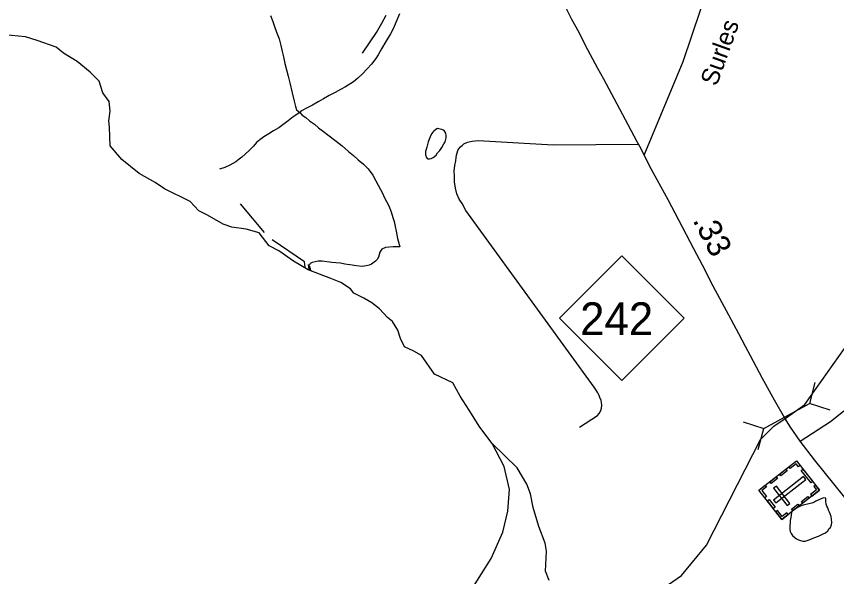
# Model space of a CAD drawing. Extents: x 2082433 to 2279600, y 546599 to 755198.
# Drawn here: x 2136702 to 2141084, y 579366 to 582358 of the extents above; entities that cross this region are included whole.
import ezdxf

# ---------------------------------------------------------------- set-up
doc = ezdxf.new("R2010")
doc.units = 0
for name, color, linetype in [('Exist Boundary Political CountyLine', 7, 'Continuous'), ('Exist Boundary Political Fire Districts', 7, 'Continuous'), ('Exist Cultural Cemetery CELL', 7, 'Continuous'), ('Exist Hydrographic Buffer Line', 7, 'Continuous'), ('Exist Hydrographic Creek Single Shore', 7, 'Continuous'), ('Exist Hydrographic Lake Shore', 7, 'Continuous'), ('Exist Hydrographic Misc Water Feature', 7, 'Continuous'), ('Exist Road Non-System Type 51', 7, 'Continuous'), ('Exist Road Primary NC Attributed', 7, 'Continuous'), ('Exist Road Primary NC Service Mileage Hundredths English Label', 7, 'Continuous'), ('Exist Road Primary NC Shield CELL', 7, 'Continuous'), ('Exist Road Primary NC Shield Number Label', 7, 'Continuous'), ('Exist Road Primary NC Structure Culvert CELL', 7, 'Continuous'), ('Exist Road Secondary Type 51 Attributed', 7, 'Continuous'), ('Exist Road Secondary Type 51 Label', 7, 'Continuous')]:
    doc.layers.add(name, color=color, linetype=linetype)

msp = doc.modelspace()

# ---------------------------------------------------------------- linework, layer by layer
at = {"layer": 'Exist Boundary Political CountyLine'}
msp.add_lwpolyline([(2139092.6, 579230.9), (2139238.1, 579462.3), (2139300.5, 579602.7), (2139327.7, 579714.5), (2139335.5, 579831.5), (2139307, 579953.7), (2139244.2, 580075.9), (2139178, 580164.1), (2139121.2, 580255.3), (2139072, 580328.8), (2139033, 580400.3), (2138936, 580446.6), (2138865.5, 580547.3), (2138825.3, 580569.6), (2138775.7, 580593.1), (2138753.9, 580637.4), (2138740.2, 580683), (2138711.7, 580728.6), (2138683.8, 580750.6), (2138642, 580796.5), (2138601, 580828), (2138558.7, 580853.5), (2138504.2, 580879.4), (2138487.8, 580902.6), (2138434.7, 580936.5), (2138382, 580958.8), (2138261.8, 581004.2), (2138181.8, 581050.4), (2138104.7, 581105.1), (2138053.5, 581132.2), (2137999.7, 581202.1), (2137929.4, 581222), (2137853.5, 581232.6), (2137806.8, 581248.5), (2137722.9, 581296.4), (2137676.6, 581319.5), (2137631.5, 581369.5), (2137493.5, 581437.1), (2137444.1, 581470.2), (2137357.5, 581519.7), (2137266.5, 581593.1), (2137203.3, 581667), (2137199.8, 581765.9), (2137195.9, 581800.3), (2137203.3, 581852.8), (2137198.8, 581903.2), (2137165, 581950.7), (2137144.7, 582012.3), (2137096.7, 582059.9), (2137027, 582117.3), (2136953.2, 582161.2), (2136915.4, 582193.1), (2136813.5, 582229.3), (2136751, 582248.8), (2136638.4, 582259.4)], dxfattribs=at)
at = {"layer": 'Exist Boundary Political Fire Districts'}
msp.add_lwpolyline([(2139547.7, 579345.7), (2139528.4, 579395), (2139534.1, 579502.3), (2139527, 579544.2), (2139492.9, 579633.5), (2139462, 579734.4), (2139448.8, 579808.4), (2139429.8, 579858.8), (2139376.5, 579947.3), (2139244.2, 580075.9), (2139178, 580164.1), (2139121.2, 580255.3), (2139072, 580328.8), (2139033, 580400.3), (2138936, 580446.6), (2138865.5, 580547.3), (2138825.3, 580569.6), (2138775.7, 580593.1), (2138753.9, 580637.4), (2138740.2, 580683), (2138711.7, 580728.6), (2138683.8, 580750.6), (2138642, 580796.5), (2138601, 580828), (2138558.7, 580853.5), (2138504.2, 580879.4), (2138487.8, 580902.6), (2138434.7, 580936.5), (2138382, 580958.8), (2138261.8, 581004.2), (2138181.8, 581050.4), (2138104.7, 581105.1), (2138053.5, 581132.2), (2137999.7, 581202.1), (2137929.4, 581222), (2137853.5, 581232.6), (2137806.8, 581248.5), (2137722.9, 581296.4), (2137676.6, 581319.5), (2137631.5, 581369.5), (2137493.5, 581437.1), (2137444.1, 581470.2), (2137357.5, 581519.7), (2137266.5, 581593.1), (2137203.3, 581667), (2137199.8, 581765.9), (2137195.9, 581800.3), (2137203.3, 581852.8), (2137198.8, 581903.2), (2137165, 581950.7), (2137144.7, 582012.3), (2137096.7, 582059.9), (2137027, 582117.3), (2136953.2, 582161.2), (2136915.4, 582193.1), (2136813.5, 582229.3), (2136751, 582248.8), (2136638.4, 582259.4)], dxfattribs=at)
at = {"layer": 'Exist Cultural Cemetery CELL'}
for points in [[(2140791.4, 579670.9), (2140668.6, 579827.7), (2140869.1, 579984.7), (2140991.8, 579827.9)], [(2140889.5, 579958.6), (2140880.5, 579951.5), (2140866.9, 579968.8), (2140835.1, 579943.9), (2140828.2, 579952.7), (2140869.1, 579984.7)], [(2140819.2, 579931.2), (2140785.1, 579904.5), (2140778.1, 579913.4), (2140812.2, 579940.1)], [(2140947.4, 579866.1), (2140895, 579932.9), (2140904, 579939.9), (2140956.3, 579873.1)], [(2140767.3, 579890.5), (2140733.2, 579863.8), (2140726.2, 579872.8), (2140760.3, 579899.5)], [(2140747.2, 579774.8), (2140758.7, 579760.1), (2140918.4, 579885.2), (2140906.9, 579899.9)], [(2140702.7, 579854.5), (2140709.7, 579845.5), (2140684.4, 579825.7), (2140709.4, 579793.8), (2140700.6, 579786.9), (2140668.6, 579827.8)], [(2140819.8, 579745), (2140834.5, 579756.5), (2140761.9, 579849.2), (2140747.2, 579837.7)], [(2140971.4, 579853.9), (2140962.4, 579846.9), (2140975.9, 579829.5), (2140944.1, 579804.6), (2140951, 579795.9), (2140991.8, 579827.9)], [(2140936.8, 579784.8), (2140902.7, 579758.1), (2140895.7, 579767), (2140929.8, 579793.8)], [(2140745.7, 579729.3), (2140713.7, 579770.1), (2140722.7, 579777.1), (2140754.7, 579736.3)], [(2140883.9, 579743.4), (2140849.8, 579716.6), (2140842.7, 579725.6), (2140876.8, 579752.3)], [(2140825.5, 579697.6), (2140818.5, 579706.6), (2140793.1, 579686.7), (2140768.1, 579718.7), (2140759.4, 579711.8), (2140791.4, 579670.9)]]:
    msp.add_lwpolyline(points, close=True, dxfattribs=at)
at = {"layer": 'Exist Hydrographic Buffer Line'}
msp.add_lwpolyline([(2138266.3, 581006.6), (2138262.2, 581032.8)], dxfattribs=at)
at = {"layer": 'Exist Hydrographic Creek Single Shore'}
for points in [[(2139844.6, 579086.3), (2140255.6, 579372.2), (2140388.7, 579533.6), (2140677.6, 580098.6), (2140748.8, 580169), (2140814.7, 580213.4), (2140913.6, 580285.2), (2141125.7, 580584.9), (2141241.7, 580753.1), (2141579.7, 581569.7), (2141695.7, 581744.5), (2141819.6, 581863.4), (2142252.7, 581982.5), (2142435.8, 582080.6), (2142617.7, 582240.9), (2143603.8, 583418.3), (2144076.8, 583887.7), (2144251.8, 584021.9), (2144525.7, 584157.4), (2145058.9, 584251.6), (2145291.8, 584194.4), (2146427.8, 583581)], [(2138026.9, 581204.3), (2137899, 581356.4)], [(2138241.5, 581046.6), (2138068.7, 581164.7)]]:
    msp.add_lwpolyline(points, dxfattribs=at)
at = {"layer": 'Exist Hydrographic Lake Shore'}
msp.add_lwpolyline([(2138244.7, 581019.5), (2138241.5, 581046.6)], dxfattribs=at)
at = {"layer": 'Exist Hydrographic Misc Water Feature'}
for points in [[(2138749.2, 582371.5), (2138729.5, 582325.5), (2138717.4, 582295.4), (2138701.6, 582265.3), (2138675.6, 582223.2), (2138652, 582185.2), (2138634.2, 582153.1), (2138622.3, 582133), (2138598.5, 582102.9), (2138576.3, 582078.9), (2138550.7, 582050.7), (2138526.7, 582028.7), (2138502.7, 582008.5), (2138460.9, 581982.4), (2138433, 581968.3), (2138405.1, 581952.1), (2138373.1, 581936), (2138343.2, 581917.9), (2138315.1, 581901.8), (2138283.3, 581883.6), (2138255.4, 581869.5), (2138221.4, 581851.4), (2138215.7, 581845.3)], [(2138059.4, 582362.5), (2138071.5, 582330.6), (2138081.8, 582304.7), (2138091.6, 582274.7), (2138106, 582238.8), (2138114.2, 582202.7), (2138122.2, 582170.8), (2138128.5, 582142.9), (2138136.5, 582106.9), (2138154.8, 582039), (2138163, 582003.1), (2138175.3, 581949.1), (2138185.5, 581905.2), (2138193.5, 581877.3), (2138199.5, 581859.3), (2138215.7, 581845.3)], [(2138215.7, 581845.3), (2138181.6, 581821.2), (2138153.7, 581801), (2138125.9, 581779), (2138103.9, 581762.9), (2138075.8, 581746.8), (2138050.2, 581730.6), (2138024.1, 581714.6), (2138002.2, 581698.4), (2137984.4, 581684.4), (2137968.4, 581664.3), (2137946.6, 581642.2), (2137924.7, 581622.1), (2137906.6, 581606), (2137892.7, 581596), (2137874.9, 581581.9), (2137858.9, 581571.9), (2137842.9, 581563.8), (2137815, 581551.7), (2137786.5, 581541.3)], [(2138215.7, 581845.3), (2138229.6, 581831.4), (2138247.7, 581817.5), (2138267.7, 581799.6), (2138294, 581781.7), (2138315.9, 581763.8), (2138342, 581743.9), (2138366, 581726), (2138410.3, 581692.3), (2138442.2, 581666.4), (2138476.5, 581636.6), (2138502.3, 581614.7), (2138528.8, 581592.8), (2138556.7, 581568.9), (2138580.7, 581543.1), (2138606.9, 581509.2), (2138622.9, 581479.3), (2138635.2, 581457.3), (2138647.1, 581433.4), (2138657.3, 581413.4), (2138669.4, 581389.5), (2138679.5, 581369.5), (2138691.6, 581345.6), (2138703.7, 581313.6), (2138713.9, 581283.7), (2138719.9, 581261.8), (2138726.2, 581235.8), (2138730.1, 581211.8), (2138734.2, 581191.8), (2138738.3, 581171.8), (2138750.4, 581128)], [(2138902, 581688.4), (2138894.2, 581660.3), (2138888.2, 581636.4), (2138888.4, 581618.3), (2138892.3, 581604.4), (2138896.4, 581598.4), (2138900.5, 581596.5), (2138908.5, 581596.5), (2138918.4, 581598.5), (2138928.4, 581604.5), (2138944.4, 581616.5), (2138952.2, 581628.6), (2138964.1, 581642.6), (2138974.2, 581658.7), (2138985.8, 581676.8), (2138992, 581688.8), (2138995.9, 581702.8), (2138997.9, 581708.8), (2138997.9, 581720.8), (2138995.7, 581734.8), (2138987.7, 581748.8), (2138975.6, 581754.7), (2138965.7, 581756.6), (2138951.6, 581758.6), (2138943.6, 581754.5), (2138931.7, 581744.5), (2138927.6, 581740.5), (2138920, 581730.5), (2138912, 581714.4), (2138902, 581688.4)], [(2138750.4, 581128), (2138714.3, 581127.8), (2138674.4, 581123.6), (2138654.7, 581115.5), (2138644.6, 581099.5), (2138636.6, 581071.4), (2138628.8, 581059.4), (2138620.8, 581051.4), (2138598.9, 581035.2), (2138587, 581029.2), (2138571, 581025.2), (2138548.9, 581023.1), (2138518.9, 581024.9), (2138482.8, 581030.8), (2138457, 581034.7), (2138433, 581040.6), (2138408.8, 581042.5), (2138386.9, 581044.3), (2138335, 581050.1), (2138314.9, 581050), (2138298.9, 581047.9), (2138282.9, 581043.9), (2138271.2, 581037.9), (2138267.1, 581027.8)], [(2138267.1, 581027.8), (2138269.2, 581015.8), (2138273.7, 581002.1), (2138276.6, 581000.4)], [(2140941.6, 579755.9), (2140905.7, 579747.8), (2140886.1, 579739.7), (2140870.1, 579731.6), (2140862.1, 579727.6), (2140854.1, 579721.5), (2140845.9, 579715.5), (2140842, 579707.5), (2140838.3, 579681.5), (2140836.2, 579665.5), (2140836.2, 579653.5), (2140834.4, 579637.5), (2140834.4, 579619.5), (2140836.4, 579607.5), (2140840.5, 579595.5), (2140848.5, 579585.6), (2140862.7, 579573.6), (2140868.6, 579567.6), (2140880.7, 579561.7), (2140890.8, 579557.8), (2140902.7, 579555.8), (2140914.8, 579555.9), (2140936.7, 579561.9), (2140962.5, 579572.1), (2140986.5, 579582.1), (2141004.4, 579590.3), (2141012.4, 579594.3), (2141024.5, 579600.3), (2141036.6, 579610.4), (2141044.2, 579622.5), (2141050.3, 579628.5), (2141056.2, 579642.5), (2141058.3, 579654.5), (2141056.2, 579672.4), (2141054, 579686.4), (2141049.9, 579700.4), (2141046, 579710.4), (2141040.1, 579720.4), (2141035.9, 579732.3), (2141031.6, 579742.3), (2141027.7, 579752.3), (2141025.7, 579766.3), (2141025.7, 579778.3), (2141025.7, 579784.3), (2141015.6, 579786.3), (2141003.8, 579782.2), (2140985.7, 579774.2), (2140971.8, 579768), (2140961.7, 579762), (2140951.7, 579758), (2140941.6, 579755.9)]]:
    msp.add_lwpolyline(points, dxfattribs=at)
at = {"layer": 'Exist Road Non-System Type 51'}
for points in [[(2138551, 582161.8), (2138625.2, 582272.3), (2138654.2, 582321.7), (2138677.1, 582365.2)], [(2139710.5, 580164.6), (2139805.8, 580226.7), (2139815.9, 580236.5), (2139824.3, 580252.3), (2139828.5, 580266.2), (2139828.9, 580282.2), (2139827.2, 580296.2), (2139825.4, 580306.3), (2139819.7, 580322.4), (2139815.9, 580332.5), (2139808.2, 580346.6), (2139798.5, 580360.8), (2139788.8, 580377), (2139103.9, 581320.7), (2139082.7, 581359.1), (2139067.2, 581381.4), (2139055.7, 581409.7), (2139048.3, 581439.8), (2139043, 581473.9), (2139041.7, 581505.9), (2139040.2, 581532), (2139044.8, 581561.9), (2139049.3, 581585.8), (2139051.7, 581603.7), (2139053.9, 581617.7), (2139060.4, 581641.6), (2139066.6, 581651.4), (2139074.8, 581661.3), (2139085, 581671.1), (2139093.1, 581676.9), (2139111.3, 581686.5), (2139127.4, 581690.2), (2139137.4, 581692), (2139169.5, 581695.3), (2139569.6, 581672.4), (2140024.8, 581675.4)]]:
    msp.add_lwpolyline(points, dxfattribs=at)
at = {"layer": 'Exist Road Primary NC Attributed'}
for points in [[(2140055.7, 581617.2), (2140038.9, 581651.2), (2140017.6, 581687.8), (2139969.7, 581778.9), (2139910.8, 581889.1), (2139839.5, 582023.2), (2139808, 582080.7), (2139742.9, 582203.6), (2139707.8, 582272.3), (2139669.7, 582341.4), (2139634.8, 582410.1)], [(2140888.4, 580089.8), (2140837.3, 580164.2), (2140807.1, 580211.4), (2140752.2, 580307.7), (2140688.1, 580423.1), (2140623.5, 580545.2), (2140597.2, 580594.8), (2140561.3, 580661.9), (2140507.9, 580762.1), (2140424.9, 580917.2), (2140366.5, 581029.2), (2140321.3, 581117), (2140241, 581269.6), (2140183, 581378.4), (2140124.9, 581485.5), (2140094.9, 581541), (2140055.7, 581617.2)], [(2141582.4, 579215.9), (2141456.6, 579376.6), (2141314.7, 579556.5), (2141271.9, 579611), (2141188.9, 579714), (2141076.4, 579852.2), (2140965.5, 579988.7), (2140888.4, 580089.8)]]:
    msp.add_lwpolyline(points, dxfattribs=at)
at = {"layer": 'Exist Road Primary NC Shield CELL'}
msp.add_lwpolyline([(2139604.2, 580745.4), (2139937.2, 581078.4), (2140270.2, 580745.4), (2139937.2, 580412.5)], close=True, dxfattribs=at)
at = {"layer": 'Exist Road Primary NC Structure Culvert CELL'}
for p, q in [((2140968, 580403.3), (2140938.3, 580290.6)), ((2140694.6, 580157.3), (2140938.3, 580290.6)), ((2141049.2, 580254.8), (2140938.3, 580290.6)), ((2140583.6, 580193.1), (2140694.6, 580157.3)), ((2140664.9, 580044.6), (2140694.6, 580157.3))]:
    msp.add_line(p, q, dxfattribs=at)
at = {"layer": 'Exist Road Secondary Type 51 Attributed'}
for points in [[(2140055.7, 581617.2), (2140264.5, 582117.1), (2140587.5, 583079), (2140621.5, 583177), (2140667.6, 583273), (2140735.9, 583393), (2140791.2, 583496.3), (2140889, 583661.9), (2140949.6, 583769.8), (2141018.1, 583900.6), (2141062.4, 583981.8), (2141108.5, 584068.5), (2141158.5, 584160.9), (2141194.9, 584237.3), (2141233.5, 584308.9), (2141261.6, 584369.4), (2141278.3, 584428.5), (2141285.6, 584480.2), (2141285.6, 584528.1), (2141312.7, 584630.1), (2141316.2, 584961.6)], [(2140888.4, 580089.8), (2141050.3, 580194.6), (2141121.1, 580250.2), (2141158.7, 580271.9), (2141186.4, 580285.8), (2141220, 580295.7), (2141257.6, 580301.6), (2141318.9, 580307.6), (2141396.1, 580321.4), (2143373, 580504.6)]]:
    msp.add_lwpolyline(points, dxfattribs=at)

# ---------------------------------------------------------------- texts
at = {"layer": 'Exist Road Primary NC Service Mileage Hundredths English Label'}
msp.add_text('.33', height=125, rotation=297.3094, dxfattribs=at).set_placement((2140312.8, 581269.6))
at = {"layer": 'Exist Road Primary NC Shield Number Label'}
msp.add_text('242', height=175, dxfattribs=at).set_placement((2139713.4, 580655.7))
at = {"layer": 'Exist Road Secondary Type 51 Label'}
msp.add_text('Surles', height=95, rotation=70.267, dxfattribs=at).set_placement((2140442.9, 581981))

doc.saveas('drawing.dxf')
